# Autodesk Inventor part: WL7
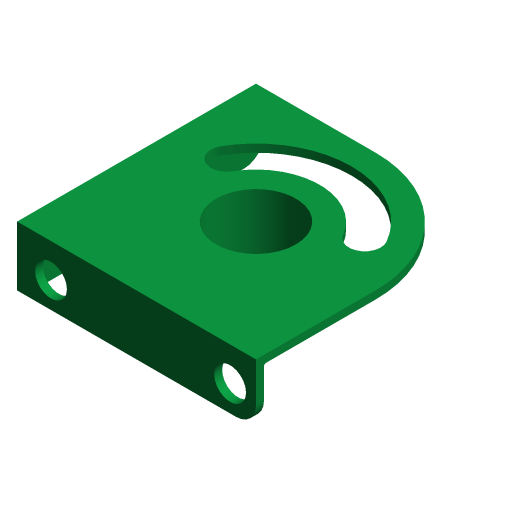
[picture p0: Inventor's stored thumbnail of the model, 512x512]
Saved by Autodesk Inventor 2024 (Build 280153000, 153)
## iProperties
Company: ATC
Shininess: 20.0
Angle Display Precision: 2
Document Length Units: 11269
Document Angle Units: 11279
Document Time Units: 11290
Document Mass Units: 11283
Document Length Units Precision: 3
Document Angle Units Precision: 2
Created: 2023-03
Part Number: WL7
Material: Kurs-AJ
Document SubType Name: Modelowanie
Designer: Andrzej Jaskulski
Density: 1 g/cm^3
Appearance: Kurs-AJ
Checked By: A.J.
Engr Approved By: Andrzej Jaskulski
Mfg Approved By: Andrzej Jaskulski
Authority: A.J.
Density: 0.0
Volumn: 0.0
Area: 0.0
PropertySet Name: Model Information
Control State: 0
Master: False
Checked Out: False
Title: A.J.: Kurs R2024-MEP
Author: Andrzej Jaskulski
Revision Number: 1/24
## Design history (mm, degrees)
node "Bryła1"
node "Początek"
  node "Płaszczyzna YZ"
  node "Płaszczyzna XZ"
  node "Płaszczyzna XY"
  node "Oś X"
  node "Oś Y"
  node "Oś Z"
derived "WP7.ipt"
feature "Bryła1::WP7.ipt" dims "d13" = 10
node "Korpusy bryłowe"
node "Korpusy powierzchniowe"
node "Punkt środkowy"
tag "Bryła wyprowadzona3"
